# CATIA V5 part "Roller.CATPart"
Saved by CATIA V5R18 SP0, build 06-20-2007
Part number: Roller
Bounding box of the stored display mesh (mm): x 0 to 20, y -10 to 10, z -10 to 10
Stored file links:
  D:\Shriniwas\v5_r19\c16_CAT_v5r19\c16_Part\Roll curve Joint\tut_4 _final\Roller.CATPart
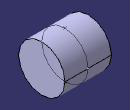
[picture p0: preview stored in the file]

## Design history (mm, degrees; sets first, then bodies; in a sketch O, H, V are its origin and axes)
Body1 (main body)
  Sketch1 on yz-plane, origin (0, 0, 0), H (0, 1, 0), V (0, 0, 1)
    circle A1 centre (0, 0) radius 10
    radius A1 = 10
  Pad1: profile Sketch1, direction (1, 0, 0), length 20
  Plane1: type Offset, Offset -10, RefPlane end face of Pad1, reversed
  Sketch2 on Plane1, origin (10, 0, 0), H (0, -1, 0), V (0, 0, 1)
    projected circle E1 centre (0, 0) radius 10 from edge [face of Pad1 from Sketch1.A1 | end face of Pad1]
    point P1 (0, -10)
    point P2 (0, 10)
    coincidence: P1 E1, P1 V, P2 V, E1 P2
